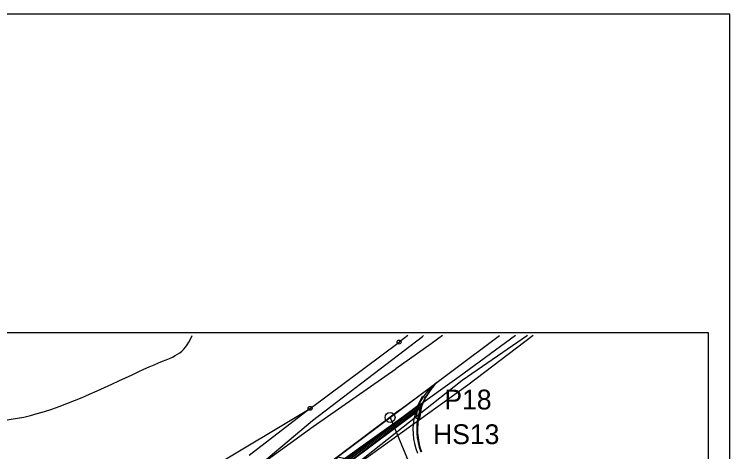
# Model space of a CAD drawing. Extents: x -495905 to -478420, y -1113297 to -1107716.
# Drawn here: x -483933.7 to -483825.3, y -1112097 to -1112030.8 of the extents above; entities that cross this region are included whole.
import ezdxf

# ---------------------------------------------------------------- set-up
doc = ezdxf.new("R2010")
doc.units = 0
for name, color, linetype in [('03_PC_OBJEKTY_STAV', 7, 'Continuous'), ('2D_VRSTEVNICE', 7, 'Continuous'), ('C11_HECTOMETRY', 7, 'Continuous'), ('C11_HLBODY', 7, 'Continuous'), ('C11_OSA', 7, 'Continuous'), ('Implicitní', 7, 'Continuous'), ('legenda', 7, 'Continuous'), ('PLYN', 7, 'Continuous'), ('pomoc', 7, 'Continuous'), ('zamereni', 7, 'Continuous'), ('ŽLAB', 7, 'Continuous')]:
    doc.layers.add(name, color=color, linetype=linetype)

# ---------------------------------------------------------------- blocks, each defined once
blk = doc.blocks.new('A$C55D')
at = {"layer": 'ŽLAB'}
for p, q in [((-7.761, 0.901), (-8.121, 0.554)), ((-8.121, 0.554), (-7.1, -0.505)), ((-6.608, -0.294), (-7.761, 0.901)), ((-6.75, -0.147), (6.75, 0.147)), ((6.456, -0.009), (8.142, 0.887)), ((7.567, 0.015), (6.708, -0.004)), ((8.377, 0.446), (7.174, -0.193)), ((8.142, 0.887), (8.377, 0.446)), ((6.708, -0.004), (-7.289, -0.309)), ((7.174, -0.193), (-7.1, -0.505)), ((-7.1, -0.505), (-6.174, -1.981)), ((-6.976, -0.703), (6.971, -0.398)), ((-5.75, -1.715), (-6.394, -0.69)), ((6.098, -0.567), (-6.301, -0.838)), ((5.398, -1.272), (6.251, -0.414)), ((7.174, -0.193), (5.752, -1.625)), ((-6.174, -1.981), (-5.75, -1.715)), ((5.752, -1.625), (5.398, -1.272))]:
    blk.add_line(p, q, dxfattribs=at)

msp = doc.modelspace()

# ---------------------------------------------------------------- linework, layer by layer
at = {"layer": '2D_VRSTEVNICE'}
msp.add_open_spline([(-483928.35, -1112101.11), (-483929.03, -1112100.29), (-483944.62, -1112095.33), (-483944.97, -1112095.06), (-483945.98, -1112094.59), (-483945.5, -1112094.13), (-483944.12, -1112091.92), (-483931.71, -1112093.31), (-483910.15, -1112082.31), (-483908.08, -1112082.43), (-483906.72, -1112079.43)], degree=3, dxfattribs=at)
at = {"layer": 'C11_HECTOMETRY'}
msp.add_circle((-483876.77, -1112091.82), 0.75, dxfattribs=at)
at = {"layer": 'C11_HLBODY'}
msp.add_circle((-483876.77, -1112091.82), 0.75, dxfattribs=at)
at = {"layer": 'C11_OSA'}
msp.add_line((-483876.77, -1112091.82), (-483869.61, -1112108.81), dxfattribs=at)
at = {"layer": 'Implicitní'}
msp.add_line((-483825.34, -1112030.79), (-484035.34, -1112030.79), dxfattribs=at)
msp.add_lwpolyline([(-483828.6, -1112213.4), (-484020.92, -1112213.4), (-484020.92, -1112078.95), (-483828.6, -1112078.95)], close=True, dxfattribs=at)
at = {"layer": 'legenda'}
msp.add_line((-483825.34, -1112327.79), (-483825.34, -1112030.79), dxfattribs=at)
at = {"layer": 'pomoc'}
for q in [(-483869.68, -1112086.52), (-483885.61, -1112098.44)]:
    msp.add_line((-483875.33, -1112090.74), q, dxfattribs=at)
for centre, radius, start, end in [((-483864.3, -1112093.74), 9, 126.7207, 202.8611), ((-483862.91, -1112093.64), 9.82, 133.5438, 200.2162), ((-483862.56, -1112093.62), 10.05, 135.0506, 199.6521)]:
    msp.add_arc(centre, radius, start, end, dxfattribs=at)
at = {"layer": 'zamereni'}
for p, q in [((-483888.54, -1112092.3), (-483871.88, -1112079.55)), ((-483874.1, -1112079.43), (-483875.41, -1112080.41)), ((-483871.88, -1112079.55), (-483871.72, -1112079.43)), ((-483868.82, -1112079.43), (-483870.56, -1112080.7)), ((-483867.4, -1112084.8), (-483860.18, -1112079.43)), ((-483857.8, -1112079.43), (-483866.32, -1112085.68)), ((-483855.96, -1112079.43), (-483865.85, -1112086.22)), ((-483855.08, -1112079.43), (-483865, -1112086.92)), ((-483888.88, -1112090.44), (-483875.41, -1112080.41)), ((-483870.56, -1112080.7), (-483875.88, -1112084.46)), ((-483888.43, -1112093.18), (-483875.88, -1112084.46)), ((-483885.61, -1112098.44), (-483867.4, -1112084.8)), ((-483866.32, -1112085.68), (-483885.29, -1112099.25)), ((-483865.85, -1112086.22), (-483884.31, -1112100.79)), ((-483865, -1112086.92), (-483884.31, -1112100.79)), ((-483908.28, -1112102.09), (-483888.88, -1112090.44)), ((-483888.88, -1112090.44), (-483898.09, -1112097.56)), ((-483896.84, -1112099.32), (-483888.54, -1112092.3)), ((-483896.84, -1112099.32), (-483888.43, -1112093.18))]:
    msp.add_line(p, q, dxfattribs=at)
for centre in [(-483875.41, -1112080.41), (-483888.88, -1112090.44)]:
    msp.add_circle(centre, 0.3, dxfattribs=at)

# ---------------------------------------------------------------- block references
at = {"layer": 'PLYN', "rotation": 35.57765689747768}
msp.add_blockref('A$C55D', (-483877.96, -1112094.06), dxfattribs=at)

# ---------------------------------------------------------------- texts
at = {"layer": '03_PC_OBJEKTY_STAV'}
for s, p in [('P18', (-483868.54, -1112090.61)), ('HS13', (-483870.25, -1112095.86))]:
    msp.add_text(s, height=3, dxfattribs=at).set_placement(p)

doc.saveas('drawing.dxf')
